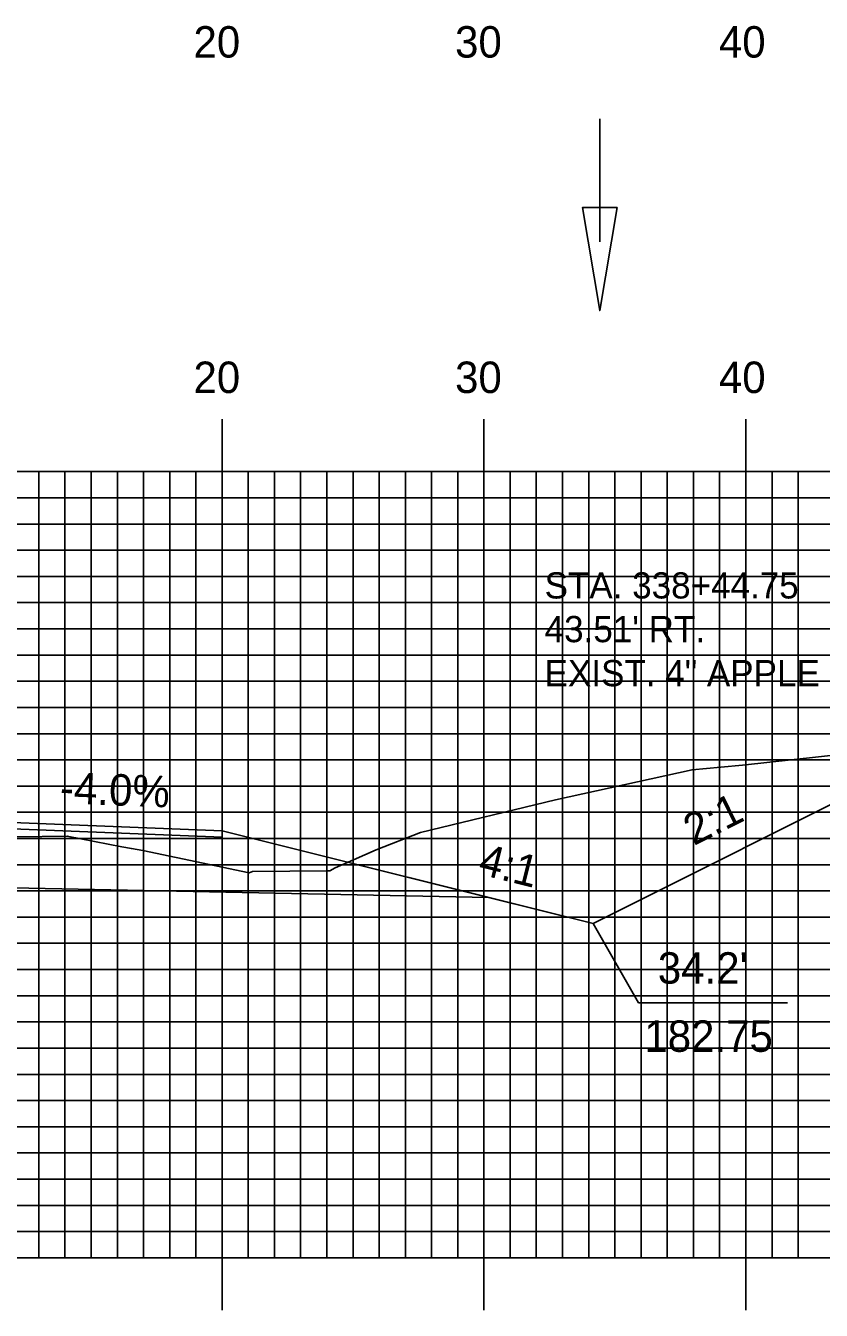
# Model space of a CAD drawing. Extents: x 1823966 to 1824309, y 442591 to 442811.
# Drawn here: x 1824144.32 to 1824174.71, y 442694.58 to 442743.61 of the extents above; entities that cross this region are included whole.
import ezdxf

# ---------------------------------------------------------------- set-up
doc = ezdxf.new("R2010")
doc.units = 0
for name, color, linetype in [('ANNOTATION', 7, 'Continuous'), ('D_Drainage_Ditch_Line', 7, 'Continuous'), ('D_Roadway_Centerline', 7, 'Continuous'), ('D_Roadway_Edge_Shoulder', 7, 'Continuous'), ('D_Roadway_SlopeLines', 7, 'Continuous'), ('D_Roadway_SubGrade', 7, 'Continuous'), ('D_Text_Monospaced', 7, 'Continuous'), ('H_V ANNOTATION', 7, 'Continuous'), ('MAJOR', 7, 'Continuous'), ('MINOR', 7, 'Continuous'), ('S_Roadway_Centerline', 7, 'Continuous')]:
    doc.layers.add(name, color=color, linetype=linetype)

msp = doc.modelspace()

# ---------------------------------------------------------------- linework, layer by layer
at = {"layer": 'ANNOTATION'}
msp.add_lwpolyline([(1824173.418, 442706.321), (1824167.727, 442706.321), (1824165.996, 442709.342)], dxfattribs=at)
at = {"layer": 'D_Drainage_Ditch_Line'}
msp.add_line((1824166.247, 442735.356), (1824166.247, 442740.055), dxfattribs=at)
msp.add_lwpolyline([(1824166.903, 442736.668), (1824165.591, 442736.668), (1824166.247, 442732.731)], close=True, dxfattribs=at)
at = {"layer": 'D_Roadway_Centerline'}
msp.add_lwpolyline([(1824101.648, 442710.342), (1824108.91, 442712.157), (1824111.822, 442712.885), (1824119.822, 442713.205), (1824131.822, 442713.445), (1824143.822, 442713.205), (1824151.822, 442712.885), (1824161.996, 442710.342), (1824165.996, 442709.342), (1824177.386, 442715.037), (1824178.636, 442715.596), (1824179.886, 442716.022), (1824181.136, 442716.317), (1824182.386, 442716.479)], dxfattribs=at)
at = {"layer": 'D_Roadway_Edge_Shoulder'}
msp.add_lwpolyline([(1824143.822, 442713.205), (1824151.822, 442712.885), (1824151.822, 442712.635), (1824143.822, 442712.955)], close=True, dxfattribs=at)
at = {"layer": 'D_Roadway_SlopeLines'}
for points in [[(1824165.996, 442709.342), (1824177.386, 442715.037), (1824178.636, 442715.596), (1824179.886, 442716.022), (1824181.136, 442716.317), (1824182.386, 442716.479)], [(1824151.822, 442712.885), (1824165.996, 442709.342)]]:
    msp.add_lwpolyline(points, dxfattribs=at)
at = {"layer": 'D_Roadway_SubGrade'}
msp.add_lwpolyline([(1824119.822, 442710.705), (1824101.648, 442710.342), (1824111.822, 442712.885), (1824111.822, 442712.635), (1824119.822, 442712.955), (1824131.822, 442713.195), (1824143.822, 442712.955), (1824151.822, 442712.635), (1824151.822, 442712.885), (1824161.996, 442710.342), (1824143.822, 442710.705), (1824131.822, 442710.945)], close=True, dxfattribs=at)
at = {"layer": 'MAJOR'}
for p, q in [((1824151.822, 442728.592), (1824151.822, 442726.588)), ((1824161.822, 442728.592), (1824161.822, 442726.588)), ((1824171.822, 442728.592), (1824171.822, 442726.588)), ((1823991.822, 442726.588), (1824271.822, 442726.588)), ((1823991.822, 442726.588), (1824271.822, 442726.588)), ((1824151.822, 442696.588), (1824151.822, 442726.588)), ((1824161.822, 442696.588), (1824161.822, 442726.588)), ((1824171.822, 442696.588), (1824171.822, 442726.588)), ((1823991.822, 442721.588), (1824271.822, 442721.588)), ((1823991.822, 442716.588), (1824271.822, 442716.588)), ((1823991.822, 442711.588), (1824271.822, 442711.588)), ((1823991.822, 442706.588), (1824271.822, 442706.588)), ((1823991.822, 442701.588), (1824271.822, 442701.588)), ((1823991.822, 442696.588), (1824271.822, 442696.588)), ((1823991.822, 442696.588), (1824271.822, 442696.588)), ((1824151.822, 442694.584), (1824151.822, 442696.588)), ((1824161.822, 442694.584), (1824161.822, 442696.588)), ((1824171.822, 442694.584), (1824171.822, 442696.588))]:
    msp.add_line(p, q, dxfattribs=at)
at = {"layer": 'MINOR'}
for p, q in [((1824144.822, 442696.588), (1824144.822, 442726.588)), ((1824145.822, 442696.588), (1824145.822, 442726.588)), ((1824146.822, 442696.588), (1824146.822, 442726.588)), ((1824147.822, 442696.588), (1824147.822, 442726.588)), ((1824148.822, 442696.588), (1824148.822, 442726.588)), ((1824149.822, 442696.588), (1824149.822, 442726.588)), ((1824150.822, 442696.588), (1824150.822, 442726.588)), ((1824152.822, 442696.588), (1824152.822, 442726.588)), ((1824153.822, 442696.588), (1824153.822, 442726.588)), ((1824154.822, 442696.588), (1824154.822, 442726.588)), ((1824155.822, 442696.588), (1824155.822, 442726.588)), ((1824156.822, 442696.588), (1824156.822, 442726.588)), ((1824157.822, 442696.588), (1824157.822, 442726.588)), ((1824158.822, 442696.588), (1824158.822, 442726.588)), ((1824159.822, 442696.588), (1824159.822, 442726.588)), ((1824160.822, 442696.588), (1824160.822, 442726.588)), ((1824162.822, 442696.588), (1824162.822, 442726.588)), ((1824163.822, 442696.588), (1824163.822, 442726.588)), ((1824164.822, 442696.588), (1824164.822, 442726.588)), ((1824165.822, 442696.588), (1824165.822, 442726.588)), ((1824166.822, 442696.588), (1824166.822, 442726.588)), ((1824167.822, 442696.588), (1824167.822, 442726.588)), ((1824168.822, 442696.588), (1824168.822, 442726.588)), ((1824169.822, 442696.588), (1824169.822, 442726.588)), ((1824170.822, 442696.588), (1824170.822, 442726.588)), ((1824172.822, 442696.588), (1824172.822, 442726.588)), ((1824173.822, 442696.588), (1824173.822, 442726.588)), ((1823991.822, 442725.588), (1824271.822, 442725.588)), ((1823991.822, 442724.588), (1824271.822, 442724.588)), ((1823991.822, 442723.588), (1824271.822, 442723.588)), ((1823991.822, 442722.588), (1824271.822, 442722.588)), ((1823991.822, 442720.588), (1824271.822, 442720.588)), ((1823991.822, 442719.588), (1824271.822, 442719.588)), ((1823991.822, 442718.588), (1824271.822, 442718.588)), ((1823991.822, 442717.588), (1824271.822, 442717.588)), ((1823991.822, 442715.588), (1824271.822, 442715.588)), ((1823991.822, 442714.588), (1824271.822, 442714.588)), ((1823991.822, 442713.588), (1824271.822, 442713.588)), ((1823991.822, 442712.588), (1824271.822, 442712.588)), ((1823991.822, 442710.588), (1824271.822, 442710.588)), ((1823991.822, 442709.588), (1824271.822, 442709.588)), ((1823991.822, 442708.588), (1824271.822, 442708.588)), ((1823991.822, 442707.588), (1824271.822, 442707.588)), ((1823991.822, 442705.588), (1824271.822, 442705.588)), ((1823991.822, 442704.588), (1824271.822, 442704.588)), ((1823991.822, 442703.588), (1824271.822, 442703.588)), ((1823991.822, 442702.588), (1824271.822, 442702.588)), ((1823991.822, 442700.588), (1824271.822, 442700.588)), ((1823991.822, 442699.588), (1824271.822, 442699.588)), ((1823991.822, 442698.588), (1824271.822, 442698.588)), ((1823991.822, 442697.588), (1824271.822, 442697.588))]:
    msp.add_line(p, q, dxfattribs=at)
at = {"layer": 'S_Roadway_Centerline'}
msp.add_lwpolyline([(1824143.98, 442712.654), (1824145.907, 442712.678), (1824147.989, 442712.271), (1824148.362, 442712.203), (1824148.8, 442712.127), (1824152.854, 442711.284), (1824152.982, 442711.332), (1824155.841, 442711.355), (1824155.942, 442711.352), (1824156.136, 442711.464), (1824156.836, 442711.769), (1824157.71, 442712.162), (1824159.394, 442712.816), (1824164.55, 442714.059), (1824169.771, 442715.212), (1824170.867, 442715.316), (1824171.695, 442715.382), (1824180.171, 442716.318), (1824189.783, 442717.016), (1824194.617, 442717.262), (1824198.985, 442717.368), (1824210.288, 442717.724)], dxfattribs=at)

# ---------------------------------------------------------------- texts
at = {"layer": 'ANNOTATION'}
for s, rotation, p in [('-4.0%', 357.7094, (1824145.613, 442713.935)), ('2:1', 26.5651, (1824169.836, 442712.298)), ('4:1', 345.9638, (1824161.557, 442711.243))]:
    msp.add_text(s, height=1.2, rotation=rotation, dxfattribs=at).set_placement(p)
for s, p in [("34.2'", (1824168.461, 442707.047)), ('182.75', (1824167.947, 442704.447))]:
    msp.add_text(s, height=1.2, dxfattribs=at).set_placement(p)
at = {"layer": 'D_Text_Monospaced'}
for s, height, p in [('STA. 338+44.75', 0.99996, (1824164.139, 442721.747)), ("43.51' RT.", 1, (1824164.139, 442720.079)), ('EXIST. 4" APPLE', 0.99996, (1824164.139, 442718.399))]:
    msp.add_text(s, height=height, dxfattribs=at).set_placement(p)
at = {"layer": 'H_V ANNOTATION'}
for s, p in [('20', (1824150.73, 442742.388)), ('30', (1824160.719, 442742.388)), ('40', (1824170.794, 442742.388)), ('20', (1824150.73, 442729.588)), ('30', (1824160.719, 442729.588)), ('40', (1824170.794, 442729.588))]:
    msp.add_text(s, height=1.2, dxfattribs=at).set_placement(p)

doc.saveas('drawing.dxf')
